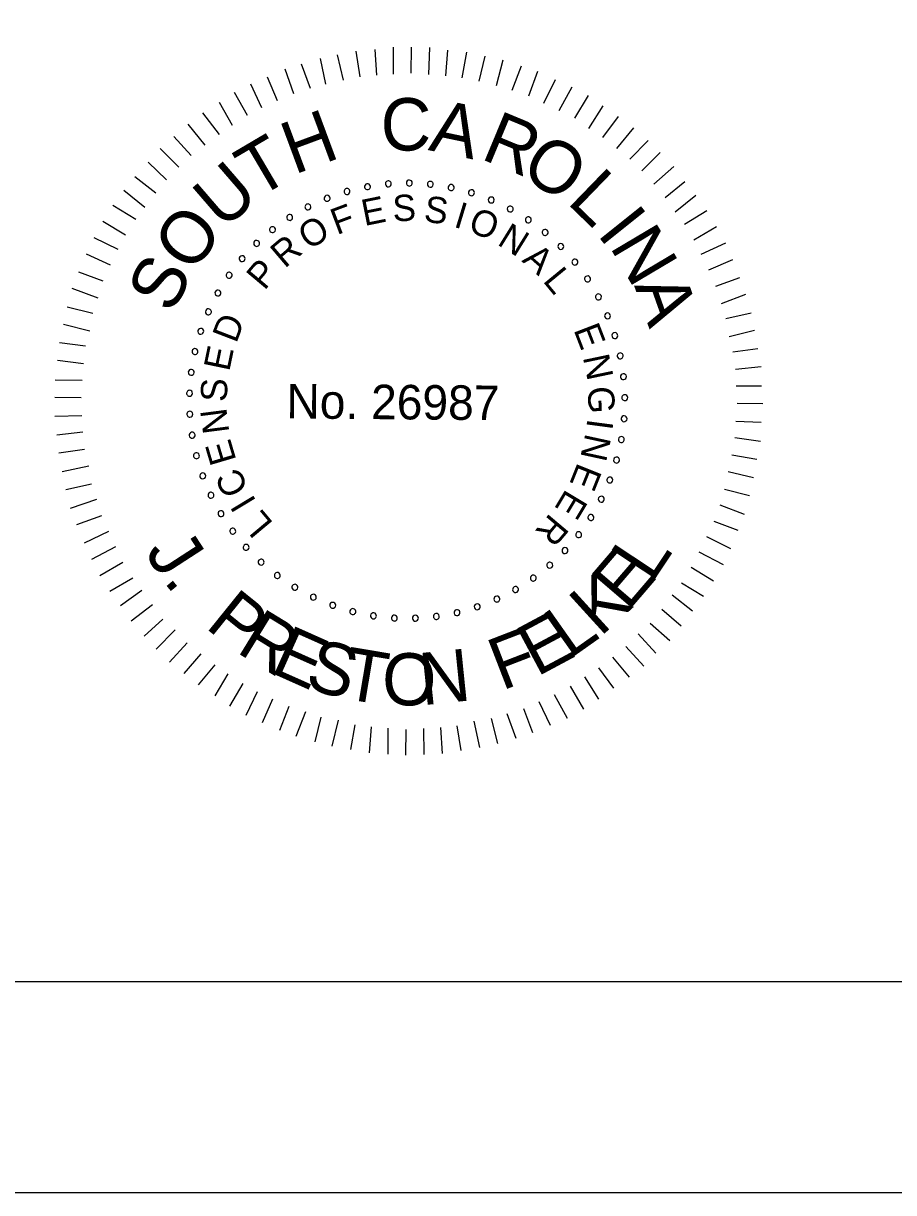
# Model space of a CAD drawing. Extents: x 2799.7 to 2896, y 515.2 to 573.9.
# Drawn here: x 2862.09 to 2867.59, y 515.22 to 522.61 of the extents above; entities that cross this region are included whole.
import ezdxf

# ---------------------------------------------------------------- set-up
doc = ezdxf.new("R2010")
doc.units = 0
for name, color, linetype in [('BR_BORDER LINES', 7, 'Continuous'), ('BR_TEXT', 7, 'Continuous'), ('Level 31', 7, 'Continuous')]:
    doc.layers.add(name, color=color, linetype=linetype)

msp = doc.modelspace()

# ---------------------------------------------------------------- linework, layer by layer
at = {"layer": 'BR_BORDER LINES'}
msp.add_line((2804.5816, 516.5558), (2894.3589, 516.5558), dxfattribs=at)
at = {"layer": 'BR_TEXT'}
for p, q in [((2864.3204, 522.2816), (2864.3103, 522.4441)), ((2864.4258, 522.2876), (2864.4272, 522.4592)), ((2864.5379, 522.2935), (2864.5393, 522.4583)), ((2864.65, 522.2858), (2864.656, 522.4573)), ((2864.7574, 522.278), (2864.7703, 522.4403)), ((2863.9996, 522.2247), (2863.9643, 522.3874)), ((2864.1097, 522.2512), (2864.072, 522.4095)), ((2864.215, 522.271), (2864.1912, 522.4336)), ((2864.8604, 522.2657), (2864.8892, 522.4279)), ((2864.9678, 522.2441), (2865.0057, 522.4018)), ((2865.0773, 522.2158), (2865.12, 522.3779)), ((2863.7976, 522.1645), (2863.7418, 522.3207)), ((2863.9032, 522.1981), (2863.8449, 522.3518)), ((2865.1755, 522.1876), (2865.234, 522.3404)), ((2865.2805, 522.1523), (2865.339, 522.3075)), ((2863.5956, 522.0747), (2863.5258, 522.224)), ((2863.6944, 522.1196), (2863.6315, 522.2689)), ((2865.3763, 522.1057), (2865.4507, 522.2539)), ((2863.5036, 522.0274), (2863.4225, 522.1722)), ((2865.472, 522.0592), (2865.5556, 522.2073)), ((2865.5723, 522.0103), (2865.6582, 522.1538)), ((2863.4093, 521.9641), (2863.3281, 522.109)), ((2865.661, 521.9455), (2865.7515, 522.089)), ((2863.3264, 521.9076), (2863.2223, 522.0435)), ((2865.7498, 521.8876), (2865.847, 522.0218)), ((2863.2366, 521.8397), (2863.1301, 521.9733)), ((2865.8362, 521.8183), (2865.9448, 521.9501)), ((2863.149, 521.774), (2863.0379, 521.8939)), ((2865.9203, 521.7511), (2866.0356, 521.8692)), ((2863.0707, 521.7015), (2862.9527, 521.8191)), ((2865.9952, 521.6773), (2866.1106, 521.7931)), ((2862.9922, 521.6197), (2862.8764, 521.7328)), ((2866.0701, 521.5942), (2866.1968, 521.7054)), ((2862.9251, 521.5356), (2862.7932, 521.6397)), ((2862.8558, 521.4469), (2862.7239, 521.5533)), ((2866.1426, 521.509), (2866.2669, 521.611)), ((2866.2059, 521.4192), (2866.3372, 521.5234)), ((2862.7979, 521.3696), (2862.6544, 521.4577)), ((2866.2647, 521.341), (2866.405, 521.4268)), ((2862.7329, 521.2717), (2862.5896, 521.3575)), ((2862.6864, 521.1805), (2862.5361, 521.255)), ((2866.3234, 521.242), (2866.466, 521.3255)), ((2866.3707, 521.1501), (2866.5247, 521.222)), ((2862.6398, 521.0825), (2862.4871, 521.1502)), ((2866.418, 521.0513), (2866.5696, 521.1165)), ((2862.5932, 520.9799), (2862.4382, 521.0384)), ((2866.4629, 520.9479), (2866.6144, 521.0039)), ((2862.5603, 520.8727), (2862.3961, 520.9334)), ((2866.4986, 520.8401), (2866.6525, 520.8983)), ((2862.5275, 520.7768), (2862.3653, 520.817)), ((2866.5253, 520.7438), (2866.6858, 520.7814)), ((2862.5083, 520.6648), (2862.3416, 520.7073)), ((2866.5472, 520.6314), (2866.7078, 520.6713)), ((2862.4801, 520.5689), (2862.3177, 520.5909)), ((2866.5694, 520.5351), (2866.7274, 520.5545)), ((2862.4677, 520.4592), (2862.3031, 520.4788)), ((2866.5867, 520.4252), (2866.7494, 520.4421)), ((2862.4599, 520.354), (2862.2883, 520.3554)), ((2866.5904, 520.3199), (2866.7507, 520.3185)), ((2862.4544, 520.2442), (2862.2874, 520.2456)), ((2866.5964, 520.21), (2866.7588, 520.2087)), ((2862.4581, 520.1297), (2862.2864, 520.1265)), ((2866.5886, 520.0956), (2866.7488, 520.0897)), ((2862.4641, 520.0267), (2862.2992, 520.0075)), ((2866.5831, 519.9926), (2866.7455, 519.9708)), ((2862.4747, 519.9168), (2862.3119, 519.8929)), ((2866.564, 519.883), (2866.7216, 519.8565)), ((2862.5012, 519.8113), (2862.3339, 519.776)), ((2866.5402, 519.7779), (2866.7001, 519.74)), ((2862.5186, 519.6989), (2862.3558, 519.6614)), ((2866.5164, 519.6659), (2866.6762, 519.6257)), ((2862.5498, 519.6004), (2862.3846, 519.5445)), ((2866.4881, 519.5678), (2866.641, 519.5093)), ((2862.581, 519.4971), (2862.425, 519.4411)), ((2866.4507, 519.4651), (2866.6012, 519.4067)), ((2862.6259, 519.3983), (2862.4721, 519.3264)), ((2866.4041, 519.3671), (2866.5545, 519.2927)), ((2862.6709, 519.3018), (2862.5193, 519.223)), ((2866.3552, 519.2714), (2866.5079, 519.19)), ((2862.7159, 519.203), (2862.5711, 519.1195)), ((2866.3063, 519.1734), (2866.4475, 519.0875)), ((2862.7792, 519.1041), (2862.6343, 519.0206)), ((2866.246, 519.0754), (2866.3849, 518.9896)), ((2862.8358, 519.0258), (2862.7022, 518.9285)), ((2866.1859, 518.9981), (2866.3155, 518.8987)), ((2862.9036, 518.936), (2862.77, 518.8318)), ((2866.1211, 518.9094), (2866.2438, 518.8031)), ((2862.9693, 518.8462), (2862.8516, 518.7373)), ((2866.0472, 518.8208), (2866.1721, 518.7099)), ((2863.0465, 518.7769), (2862.9266, 518.6566)), ((2865.971, 518.7527), (2866.0845, 518.6305)), ((2863.1236, 518.6962), (2863.0105, 518.5736)), ((2865.8949, 518.6733), (2866.0082, 518.5488)), ((2863.2101, 518.6269), (2863.1015, 518.5018)), ((2865.8097, 518.6054), (2865.9161, 518.4785)), ((2863.2988, 518.5574), (2863.1924, 518.4302)), ((2865.7221, 518.5374), (2865.8172, 518.4085)), ((2863.3807, 518.4995), (2863.2972, 518.3607)), ((2865.6324, 518.4809), (2865.7205, 518.3407)), ((2863.474, 518.4393), (2863.3905, 518.2958)), ((2863.5651, 518.3859), (2863.4929, 518.2377)), ((2865.5427, 518.4222), (2865.6262, 518.2773)), ((2863.6631, 518.3393), (2863.5978, 518.1911)), ((2865.3451, 518.3254), (2865.417, 518.176)), ((2865.4416, 518.3704), (2865.5227, 518.2209)), ((2863.7656, 518.2927), (2863.7073, 518.1421)), ((2863.8707, 518.2598), (2863.8099, 518.1047)), ((2863.9665, 518.2269), (2863.9286, 518.0694)), ((2865.143, 518.2493), (2865.1989, 518.0932)), ((2865.2486, 518.2804), (2865.3045, 518.1289)), ((2864.0763, 518.2078), (2864.0359, 518.0433)), ((2864.1812, 518.1771), (2864.1548, 518.0217)), ((2864.2864, 518.1648), (2864.2736, 518.0001)), ((2864.3917, 518.1571), (2864.3903, 517.9923)), ((2864.6159, 518.1552), (2864.6191, 517.9904)), ((2864.7234, 518.1612), (2864.7336, 517.9963)), ((2864.8265, 518.1717), (2864.8528, 518.016)), ((2864.9344, 518.2007), (2864.9696, 518.0355)), ((2865.0443, 518.218), (2865.0843, 518.0598)), ((2864.5037, 518.1493), (2864.5023, 517.9868))]:
    msp.add_line(p, q, dxfattribs=at)
for centre, start, end in [((2864.1327, 521.5469), 16.14222, 196.14222), ((2864.1327, 521.5469), 196.14222, 16.14222), ((2864.262, 521.5774), 10.60376, 190.60376), ((2864.262, 521.5774), 190.60376, 10.60376), ((2864.3937, 521.5953), 5.06529, 185.06529), ((2864.3937, 521.5953), 185.06529, 5.06529), ((2864.5265, 521.6003), 359.52683, 179.52683), ((2864.5265, 521.6003), 179.52683, 359.52683), ((2864.6591, 521.5925), 173.98837, 353.98837), ((2864.6591, 521.5925), 353.98837, 173.98837), ((2864.7904, 521.572), 168.44991, 348.44991), ((2864.7904, 521.572), 348.44991, 168.44991), ((2864.9191, 521.5389), 342.91145, 162.91145), ((2864.0069, 521.5041), 21.68068, 201.68068), ((2864.0069, 521.5041), 201.68068, 21.68068), ((2864.9191, 521.5389), 162.91145, 342.91145), ((2865.044, 521.4935), 157.37299, 337.37299), ((2865.044, 521.4935), 337.37299, 157.37299), ((2863.8858, 521.4494), 27.21914, 207.21914), ((2863.8858, 521.4494), 207.21914, 27.21914), ((2865.1639, 521.4363), 151.83453, 331.83453), ((2865.1639, 521.4363), 331.83453, 151.83453), ((2863.7706, 521.3832), 32.7576, 212.7576), ((2863.7706, 521.3832), 212.7576, 32.7576), ((2865.2778, 521.3677), 146.29606, 326.29606), ((2865.2778, 521.3677), 326.29606, 146.29606), ((2863.6623, 521.3062), 38.29606, 218.29606), ((2863.6623, 521.3062), 218.29606, 38.29606), ((2865.3845, 521.2885), 140.7576, 320.7576), ((2865.3845, 521.2885), 320.7576, 140.7576), ((2863.5619, 521.2191), 43.83453, 223.83453), ((2863.5619, 521.2191), 223.83453, 43.83453), ((2865.483, 521.1994), 135.21914, 315.21914), ((2865.483, 521.1994), 315.21914, 135.21914), ((2863.4704, 521.1227), 49.37299, 229.37299), ((2863.4704, 521.1227), 229.37299, 49.37299), ((2865.5725, 521.1012), 129.68068, 309.68068), ((2865.5725, 521.1012), 309.68068, 129.68068), ((2863.3887, 521.0179), 54.91145, 234.91145), ((2863.3887, 521.0179), 234.91145, 54.91145), ((2865.6521, 520.9948), 124.14222, 304.14222), ((2865.6521, 520.9948), 304.14222, 124.14222), ((2863.3174, 520.9058), 60.44991, 240.44991), ((2863.3174, 520.9058), 240.44991, 60.44991), ((2865.7211, 520.8812), 118.60376, 298.60376), ((2865.7211, 520.8812), 298.60376, 118.60376), ((2863.2573, 520.7873), 65.98837, 245.98837), ((2863.2573, 520.7873), 245.98837, 65.98837), ((2865.7787, 520.7615), 113.06529, 293.06529), ((2865.7787, 520.7615), 293.06529, 113.06529), ((2863.2089, 520.6635), 71.52683, 251.52683), ((2863.2089, 520.6635), 251.52683, 71.52683), ((2865.8246, 520.6367), 107.52683, 287.52683), ((2865.8246, 520.6367), 287.52683, 107.52683), ((2863.1727, 520.5357), 77.06529, 257.06529), ((2863.1727, 520.5357), 257.06529, 77.06529), ((2865.8582, 520.5082), 101.98837, 281.98837), ((2865.8582, 520.5082), 281.98837, 101.98837), ((2863.149, 520.4049), 82.60376, 262.60376), ((2863.149, 520.4049), 262.60376, 82.60376), ((2865.8792, 520.377), 96.44991, 276.44991), ((2865.8792, 520.377), 276.44991, 96.44991), ((2863.138, 520.2725), 88.14222, 268.14222), ((2863.138, 520.2725), 268.14222, 88.14222), ((2865.8875, 520.2443), 90.91145, 270.91145), ((2865.8875, 520.2443), 270.91145, 90.91145), ((2863.1398, 520.1396), 93.68068, 273.68068), ((2863.1398, 520.1396), 273.68068, 93.68068), ((2865.8829, 520.1115), 85.37299, 265.37299), ((2865.8829, 520.1115), 265.37299, 85.37299), ((2863.1545, 520.0075), 99.21914, 279.21914), ((2863.1545, 520.0075), 279.21914, 99.21914), ((2865.8655, 519.9798), 79.83453, 259.83453), ((2865.8655, 519.9798), 259.83453, 79.83453), ((2863.1818, 519.8775), 104.7576, 284.7576), ((2863.1818, 519.8775), 284.7576, 104.7576), ((2865.8355, 519.8503), 74.29606, 254.29606), ((2865.8355, 519.8503), 254.29606, 74.29606), ((2863.2216, 519.7507), 110.29606, 290.29606), ((2863.2216, 519.7507), 290.29606, 110.29606), ((2865.7932, 519.7244), 68.7576, 248.7576), ((2865.7932, 519.7244), 248.7576, 68.7576), ((2863.2734, 519.6283), 115.83453, 295.83453), ((2863.2734, 519.6283), 295.83453, 115.83453), ((2865.7389, 519.6031), 63.21914, 243.21914), ((2865.7389, 519.6031), 243.21914, 63.21914), ((2863.3368, 519.5116), 121.37299, 301.37299), ((2863.3368, 519.5116), 301.37299, 121.37299), ((2865.6731, 519.4876), 57.68068, 237.68068), ((2865.6731, 519.4876), 237.68068, 57.68068), ((2863.4112, 519.4014), 126.91145, 306.91145), ((2863.4112, 519.4014), 306.91145, 126.91145), ((2865.5965, 519.379), 52.14222, 232.14222), ((2865.5965, 519.379), 232.14222, 52.14222), ((2863.4958, 519.299), 132.44991, 312.44991), ((2863.4958, 519.299), 312.44991, 132.44991), ((2865.5098, 519.2784), 46.60376, 226.60376), ((2865.5098, 519.2784), 226.60376, 46.60376), ((2863.59, 519.2052), 137.98837, 317.98837), ((2863.59, 519.2052), 317.98837, 137.98837), ((2865.4137, 519.1865), 41.06529, 221.06529), ((2865.4137, 519.1865), 221.06529, 41.06529), ((2863.6927, 519.1209), 143.52683, 323.52683), ((2863.6927, 519.1209), 323.52683, 143.52683), ((2865.3093, 519.1044), 35.52683, 215.52683), ((2865.3093, 519.1044), 215.52683, 35.52683), ((2863.8031, 519.047), 149.06529, 329.06529), ((2863.8031, 519.047), 329.06529, 149.06529), ((2865.1974, 519.0327), 29.98837, 209.98837), ((2865.1974, 519.0327), 209.98837, 29.98837), ((2863.9201, 518.984), 154.60376, 334.60376), ((2863.9201, 518.984), 334.60376, 154.60376), ((2865.0791, 518.9722), 24.44991, 204.44991), ((2865.0791, 518.9722), 204.44991, 24.44991), ((2864.0427, 518.9327), 160.14222, 340.14222), ((2864.0427, 518.9327), 340.14222, 160.14222), ((2864.1696, 518.8934), 165.68068, 345.68068), ((2864.1696, 518.8934), 345.68068, 165.68068), ((2864.8278, 518.8866), 13.37299, 193.37299), ((2864.8278, 518.8866), 193.37299, 13.37299), ((2864.9555, 518.9233), 18.91145, 198.91145), ((2864.9555, 518.9233), 198.91145, 18.91145), ((2864.2998, 518.8665), 171.21914, 351.21914), ((2864.2998, 518.8665), 351.21914, 171.21914), ((2864.4319, 518.8523), 356.7576, 176.7576), ((2864.4319, 518.8523), 176.7576, 356.7576), ((2864.5648, 518.851), 2.29606, 182.29606), ((2864.5648, 518.851), 182.29606, 2.29606), ((2864.6971, 518.8624), 7.83453, 187.83453), ((2864.6971, 518.8624), 187.83453, 7.83453)]:
    msp.add_arc(centre, 0.0187, start, end, dxfattribs=at)
at = {"layer": 'Level 31'}
msp.add_lwpolyline([(2799.6927, 573.89), (2799.6927, 515.2226), (2895.6939, 515.2226), (2895.6939, 573.89)], dxfattribs=at)

# ---------------------------------------------------------------- texts
at = {"layer": 'BR_TEXT'}
for s, height, rotation, p in [('C', 0.3309, 359.54822, (2864.3439, 521.8072)), ('A', 0.3309, 348.19813, (2864.641, 521.8093)), ('H', 0.3309, 20.36371, (2863.7987, 521.6518)), ('R', 0.3309, 337.43439, (2864.9696, 521.7564)), ('T', 0.3309, 30.49921, (2863.5643, 521.4983)), ('O', 0.3305, 326.58689, (2865.2156, 521.6583)), ('U', 0.3309, 40.80225, (2863.3479, 521.299)), ('L', 0.3309, 315.94879, (2865.5158, 521.4776)), ('E', 0.166, 11.41035, (2864.2426, 521.3285)), ('S', 0.166, 2.20798, (2864.4234, 521.3578)), ('S', 0.166, 352.66081, (2864.6135, 521.3573)), ('I', 0.166, 343.11363, (2864.8008, 521.3252)), ('O', 0.3309, 52.0267, (2863.1491, 521.0218)), ('F', 0.166, 20.61271, (2864.0688, 521.2707)), ('O', 0.166, 338.43918, (2864.8899, 521.2982)), ('I', 0.3309, 308.66128, (2865.7061, 521.2795)), ('O', 0.166, 30.84774, (2863.8891, 521.1747)), ('N', 0.166, 328.20415, (2865.0756, 521.2145)), ('N', 0.3309, 300.70365, (2865.7878, 521.2011)), ('R', 0.166, 40.39491, (2863.7394, 521.0576)), ('A', 0.166, 318.65698, (2865.2328, 521.1077)), ('S', 0.3305, 63.25114, (2863.0281, 520.7669)), ('P', 0.166, 49.94209, (2863.6112, 520.9174)), ('L', 0.166, 309.45461, (2865.3656, 520.9815)), ('A', 0.3309, 289.47921, (2865.9457, 520.953)), ('D', 0.166, 69.03644, (2863.4327, 520.5833)), ('E', 0.166, 291.049, (2865.5626, 520.674)), ('E', 0.166, 78.23881, (2863.3885, 520.4055)), ('N', 0.166, 281.84664, (2865.6218, 520.5006)), ('S', 0.166, 87.78598, (2863.3733, 520.2161)), ('No. 26987', 0.21799, 359.52683, (2863.7495, 520.1136)), ('G', 0.166, 272.29946, (2865.6531, 520.3132)), ('N', 0.166, 97.33316, (2863.3897, 520.0268)), ('I', 0.166, 262.40836, (2865.6522, 520.1163)), ('N', 0.166, 257.73391, (2865.64, 520.024)), ('E', 0.166, 106.53552, (2863.435, 519.8493)), ('C', 0.166, 116.42662, (2863.5147, 519.6692)), ('E', 0.166, 248.18673, (2865.5919, 519.8401)), ('E', 0.166, 238.98437, (2865.5174, 519.6728)), ('I', 0.166, 121.10107, (2863.5629, 519.5895)), ('L', 0.166, 129.95951, (2863.6713, 519.4504)), ('R', 0.166, 229.78201, (2865.417, 519.5195)), ('J', 0.3295, 302.95589, (2862.8502, 519.2679)), ('E', 0.3295, 49.3639, (2865.9063, 518.8895)), ('L', 0.3295, 56.42474, (2866.0595, 519.0701)), ('K', 0.3295, 42.30307, (2865.732, 518.7292)), ('.', 0.3295, 309.39736, (2862.9678, 519.0866)), ('P', 0.3295, 321.10348, (2863.2303, 518.7953)), ('R', 0.3295, 328.53593, (2863.4257, 518.6405)), ('E', 0.3295, 28.1814, (2865.3312, 518.4785)), ('L', 0.3295, 35.24223, (2865.5394, 518.5915)), ('E', 0.3295, 335.96839, (2863.6394, 518.5123)), ('F', 0.3295, 21.12057, (2865.1108, 518.392)), ('S', 0.3295, 343.02922, (2863.8562, 518.417)), ('T', 0.3295, 350.46168, (2864.0952, 518.3463)), ('O', 0.3295, 358.14189, (2864.3496, 518.3064)), ('N', 0.3295, 5.82209, (2864.6071, 518.3009))]:
    msp.add_text(s, height=height, rotation=rotation, dxfattribs=at).set_placement(p)

doc.saveas('drawing.dxf')
